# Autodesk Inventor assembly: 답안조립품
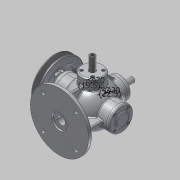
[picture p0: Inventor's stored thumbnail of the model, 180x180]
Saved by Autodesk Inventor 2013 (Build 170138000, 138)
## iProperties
Created: 2016-07
Part Number: 답안조립품
Document SubType Name: Assembly
Designer: dgall
Mass: 3970.14 g
Surface Area: 2574.68 cm^2
Volume: 982.855 cm^3
Density: 4.03939 g/cm^3
Author: dgall
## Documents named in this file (17)
- C:\Users\dgall\Desktop\360707V1025\답안조립품.iam
- C:\Users\dgall\Desktop\360707V1025\본체.ipt
- C:\Users\dgall\Desktop\360707V1025\본체커버.ipt
- C:\Users\dgall\Desktop\360707V1025\베어링- 6202.ipt
- C:\Users\dgall\Desktop\360707V1025\앞커버.ipt
- C:\Users\dgall\Desktop\360707V1025\뒤커버.ipt
- C:\Users\dgall\Desktop\360707V1025\슬라이드 커버.ipt
- C:\Users\dgall\Desktop\360707V1025\축.ipt
- C:\Users\dgall\Desktop\360707V1025\오일실.ipt
- C:\Users\dgall\Desktop\360707V1025\키-4x4.ipt
- C:\Users\dgall\Desktop\360707V1025\V-벨트풀리.ipt
- C:\Users\dgall\Desktop\360707V1025\와셔 8x17.ipt
- C:\Users\dgall\Desktop\360707V1025\너트-M8x1.ipt
- C:\Users\dgall\Desktop\360707V1025\볼트 M4x0.7.ipt
- C:\Users\dgall\Desktop\360707V1025\스프링1.ipt
- C:\Users\dgall\Desktop\360707V1025\스프링2.ipt
- C:\Users\dgall\Desktop\360707V1025\슬라이드.ipt
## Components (18 placed, 2 different names)
1. V-벨트풀리:1
2. M4x0.7x12:3
3. M4x0.7x12:1
4. M4x0.7x12:6
5. M4x0.7x12:7
6. M4x0.7x12:8
7. M4x0.7x12:4
8. M4x0.7x12:9
9. M4x0.7x12:10
10. M4x0.7x12:11
11. M4x0.7x12:5
12. M4x0.7x12:12
13. M4x0.7x12:13
14. M4x0.7x12:14
15. M4x0.7x12:2
16. M4x0.7x12:15
17. M4x0.7x12:16
18. M4x0.7x12:17
